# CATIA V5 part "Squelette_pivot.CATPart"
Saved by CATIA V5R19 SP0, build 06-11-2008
Part number: Squelette_pivot
Bounding box of the stored display mesh (mm): x 25 to 25, y 20 to 20, z 0 to 0
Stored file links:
  F:\IAO\Catia\Squelette_pivot.CATPart
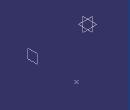
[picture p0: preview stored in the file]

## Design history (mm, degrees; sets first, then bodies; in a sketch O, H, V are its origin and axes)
Body1 (main body)
  Point1: (25, 20, 0)
  Plane1: type Offset, Offset 25, RefPlane yz-plane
